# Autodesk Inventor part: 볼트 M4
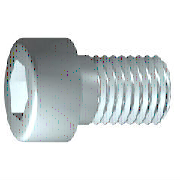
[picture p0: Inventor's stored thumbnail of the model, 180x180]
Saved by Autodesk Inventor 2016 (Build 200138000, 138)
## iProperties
IsCustomPart: 1
Created: 2012-02
Part Number: 볼트 M4
Material: 스테인리스강
Description: 6각 소켓 머리 캡 나사
Document SubType Name: Modeling
Standard: ISO 4762
Designer: mduedu
Standard Revision: Fourth edition 2004-03-01
Standards Organization: ISO
Language: ko-KR
Size Designation: M4 x 10
Categories: <MemberInstance><Categories><Category DisplayName="조임쇠" InternalName="e4da775c-781d-43d5-af7c-5136215cf5a6" Mnemonic="FSTN"><Category DisplayName="볼트" InternalN
Density: 8.08 g/cm^3
Appearance: 반광택
Mass: 2.0939 g
Surface Area: 3.06255 cm^2
Volume: 0.259146 cm^3
Author: mduedu
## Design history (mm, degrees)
sketch "스케치1"
  geometry: L1 (-1, 0)-(10, 0); L2 (10, 0)-(10, 2); L3 (10, 2)-(1.75, 2); L4 (1.75, 2)-(1.32, 2); L5 (1.32, 2)-(0, 2); L6 (0, 2)-(0, 3.5); L7 (0, 3.5)-(-4, 3.5); L8 (-4, 3.5)-(-4, 1.732); L9 (-4, 1.732)-(-2, 1.732); L10 (-2, 1.732)-(-1, 0); L11 (-6.8, 0)-(12.8, 0) reference; L12 (0, -0.7)-(0, 4.2) reference; L13 (1.75, 2)-(0, 2)
  constraints: 22 end point, 6 parallel, 2 collinear, 2 perpendicular, 1 horizontal, 1 point on line
  dimensions: "d1" = 8.25 distance from line of L3.end L2 (= GEL); "d2" = 0.42952 distance of L4.end L3.end (computed from GAL); "d3" = 4 distance between parallel lines of L8 L6 (= KOH); "d4" = 2 distance of L8.end L9.end (= INTI); "d5" = 60 deg angle of L10 L1; "d6" = 4 diameter of L3 L1 (= GD); "d7" = 4 diameter of L5 L1 (= BDM); "d8" = 3.4641 diameter of L9 L1 (= 1.1547 x SW); "d9" = 7 diameter of L7 L1 (= KOD); "d26" = 10 distance between parallel lines of L12 L2 (= NLG)
revolve "본체" sketch "스케치1" stored, may be unused: angle "d10" = 90 deg
sketch "스케치2"
  geometry: L1 (0, -4.9)-(0, 4.9) reference; L2 (-4.9, 0)-(4.9, 0) reference; L3 (1.732, 0)-(0.866, -1.5); L4 (0.866, -1.5)-(-0.866, -1.5); L5 (-0.866, -1.5)-(-1.732, 0); L6 (-1.732, 0)-(-0.866, 1.5); L7 (-0.866, 1.5)-(0.866, 1.5); L8 (0.866, 1.5)-(1.732, 0); 2 further points
  constraints: 12 end point, 1 coincident, 1 horizontal alignment, 1 point on line, 12 other
extrude "슬롯" join sketch "스케치2" stored distance "d11" = 10; taper "d12" = 0 deg
workplane "Work Plane1"
body "Solid1"
fillet "모깎기1" dims "d17" = 0.4 (= RR)
feature "스레드" dims "d13" = 8.25 (= GEL), "d14" = 0
chamfer "모따기1" distance "d15" = 0.42941 (= -0.5 x SPD + 0.5 x GD); stored, may be unused: second distance "d16" = 0.42941 (= GUL), angle "d27" = 45 deg
other parameters: "GD" = 4 [user parameter; used in 2 equation terms], "NLG" = 10 [user parameter; used in 1 equation term], "GEL" = 8.25 [user parameter; used in 2 equation terms], "KOD" = 7 [user parameter; used in 1 equation term], "KOH" = 4 [user parameter; used in 1 equation term], "INTI" = 2 [user parameter; used in 1 equation term], "GAL" = 0.42941 (= 0.61345 x PTC) [user parameter; used in 1 equation term], "GUL" = 0.42941 (= 0.61345 x PTC) [user parameter; used in 1 equation term], "BDM" = 4 (= NND) [user parameter; used in 1 equation term], "SW" = 3 [user parameter; used in 2 equation terms], "RR" = 0.4 [user parameter; used in 1 equation term], "SPD" = 3.14117 (= NND - 1.2269 x PTC) [user parameter; used in 1 equation term], "d19" = 0, "d28" = 0, "d29" = 0, "R" = 0.1 [user parameter], "TOA" = 30 deg [user parameter], "GD1" = 3.14117 (= THREADDIA - 1.2269 x PTC) [user parameter], "THREADDIA" = 4 [user parameter; used in 1 equation term], "FAWI" = 45 deg [user parameter], "TPU" = 14.28571 (computed from PTC) [user parameter], "PTC" = 0.7 [user parameter; used in 5 equation terms], "NND" = 4 [user parameter; used in 2 equation terms], "E0" = 3.465 (= 1.155 x SW) [user parameter]
